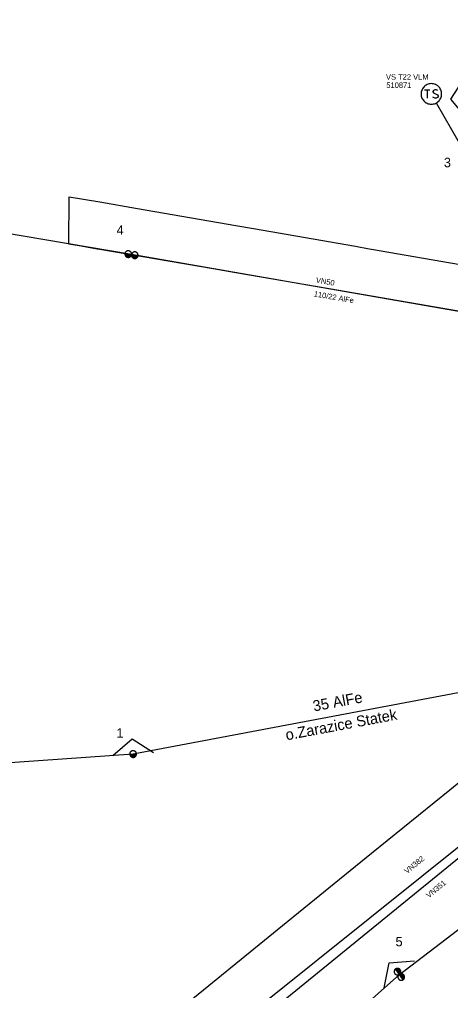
# Model space of a CAD drawing. Extents: x -545588 to -543214, y -1196037 to -1194452.
# Drawn here: x -545402.3 to -545323, y -1195024.5 to -1194845.7 of the extents above; entities that cross this region are included whole.
import ezdxf

# ---------------------------------------------------------------- set-up
doc = ezdxf.new("R2010")
doc.units = 0
for name, color, linetype in [('DOPLŇ_POPISY', 7, 'Continuous'), ('ELE_EON', 7, 'Continuous'), ('ELE_EON_POPIS', 7, 'Continuous'), ('POL_ZNAČKA_PRACOVNÍ', 7, 'Continuous'), ('SDEL_EON', 7, 'Continuous'), ('Vrstva 18', 7, 'Continuous'), ('Vrstva 25', 7, 'Continuous'), ('Vrstva 26', 7, 'Continuous'), ('Vrstva 27', 7, 'Continuous'), ('Vrstva 35', 7, 'Continuous'), ('Vrstva 52', 7, 'Continuous'), ('Vrstva 53', 7, 'Continuous'), ('Vrstva 54', 7, 'Continuous'), ('ZP_EON', 7, 'Continuous'), ('ZP_EON_POPIS', 7, 'Continuous')]:
    doc.layers.add(name, color=color, linetype=linetype)

# ---------------------------------------------------------------- blocks, each defined once
blk = doc.blocks.new('VN860')
at = {"layer": 'POL_ZNAČKA_PRACOVNÍ'}
for points in [[(-3.74, 0), (0.01, 2.82)], [(0.01, 2.82), (3.76, 0)]]:
    blk.add_lwpolyline(points, dxfattribs=at)
blk = doc.blocks.new('VN440')
at = {"layer": 'ELE_EON_POPIS'}
for points in [[(1.22, 0), (1.21, 0.13), (1.19, 0.25), (1.16, 0.38), (1.11, 0.5), (1.05, 0.61), (0.98, 0.72), (0.9, 0.82), (0.81, 0.91), (0.71, 0.99), (0.6, 1.06), (0.49, 1.12), (0.37, 1.16), (0.25, 1.2), (0.12, 1.22), (-0.01, 1.22), (-0.14, 1.22), (-0.26, 1.2), (-0.39, 1.16), (-0.51, 1.12), (-0.62, 1.06), (-0.73, 0.99), (-0.83, 0.91), (-0.92, 0.82), (-1, 0.72), (-1.07, 0.61), (-1.13, 0.5), (-1.18, 0.38), (-1.21, 0.25), (-1.23, 0.13), (-1.24, 0), (-1.23, -0.13), (-1.21, -0.26), (-1.18, -0.38), (-1.13, -0.5), (-1.07, -0.62), (-1, -0.73), (-0.92, -0.83), (-0.83, -0.92), (-0.73, -1), (-0.62, -1.07), (-0.51, -1.13), (-0.39, -1.17), (-0.26, -1.2), (-0.14, -1.23), (-0.01, -1.23), (0.12, -1.23), (0.25, -1.2), (0.37, -1.17), (0.49, -1.13), (0.6, -1.07), (0.71, -1), (0.81, -0.92), (0.9, -0.83), (0.98, -0.73), (1.05, -0.62), (1.11, -0.5), (1.16, -0.38), (1.19, -0.26), (1.21, -0.13), (1.22, 0)], [(-1.24, 0), (1.22, 0)], [(-1.18, -0.34), (1.1, -0.34)], [(-1.01, -0.63), (0.97, -0.63)], [(-0.74, -0.92), (0.68, -0.92)]]:
    blk.add_lwpolyline(points, dxfattribs=at)
blk = doc.blocks.new('VN450')
at = {"layer": 'ELE_EON_POPIS'}
for points in [[(0, 0), (-0.01, 0.13), (-0.03, 0.25), (-0.06, 0.38), (-0.11, 0.5), (-0.16, 0.61), (-0.23, 0.72), (-0.31, 0.82), (-0.4, 0.91), (-0.5, 0.99), (-0.61, 1.06), (-0.72, 1.11), (-0.84, 1.16), (-0.97, 1.19), (-1.09, 1.21), (-1.22, 1.22), (-1.35, 1.21), (-1.47, 1.19), (-1.59, 1.16), (-1.71, 1.11), (-1.83, 1.06), (-1.93, 0.99), (-2.03, 0.91), (-2.12, 0.82), (-2.2, 0.72), (-2.27, 0.61), (-2.33, 0.5), (-2.38, 0.38), (-2.41, 0.25), (-2.43, 0.13), (-2.44, 0), (-2.43, -0.13), (-2.41, -0.25), (-2.38, -0.38), (-2.33, -0.5), (-2.27, -0.61), (-2.2, -0.72), (-2.12, -0.82), (-2.03, -0.91), (-1.93, -0.99), (-1.83, -1.06), (-1.71, -1.11), (-1.59, -1.16), (-1.47, -1.19), (-1.35, -1.21), (-1.22, -1.22), (-1.09, -1.21), (-0.97, -1.19), (-0.84, -1.16), (-0.72, -1.11), (-0.61, -1.06), (-0.5, -0.99), (-0.4, -0.91), (-0.31, -0.82), (-0.23, -0.72), (-0.16, -0.61), (-0.11, -0.5), (-0.06, -0.38), (-0.03, -0.25), (-0.01, -0.13), (0, 0)], [(-2.44, 0), (2.44, 0)], [(2.44, 0), (2.43, 0.13), (2.41, 0.25), (2.38, 0.38), (2.33, 0.5), (2.27, 0.61), (2.2, 0.72), (2.12, 0.82), (2.03, 0.91), (1.94, 0.99), (1.83, 1.06), (1.71, 1.11), (1.6, 1.16), (1.47, 1.19), (1.35, 1.21), (1.22, 1.22), (1.09, 1.21), (0.97, 1.19), (0.84, 1.16), (0.72, 1.11), (0.61, 1.06), (0.5, 0.99), (0.4, 0.91), (0.31, 0.82), (0.23, 0.72), (0.16, 0.61), (0.11, 0.5), (0.06, 0.38), (0.03, 0.25), (0.01, 0.13), (0, 0), (0.01, -0.13), (0.03, -0.25), (0.06, -0.38), (0.11, -0.5), (0.16, -0.61), (0.23, -0.72), (0.31, -0.82), (0.4, -0.91), (0.5, -0.99), (0.61, -1.06), (0.72, -1.11), (0.84, -1.16), (0.97, -1.19), (1.09, -1.21), (1.22, -1.22), (1.35, -1.21), (1.47, -1.19), (1.6, -1.16), (1.71, -1.11), (1.83, -1.06), (1.94, -0.99), (2.03, -0.91), (2.12, -0.82), (2.2, -0.72), (2.27, -0.61), (2.33, -0.5), (2.38, -0.38), (2.41, -0.25), (2.43, -0.13), (2.44, 0)], [(-2.4, -0.31), (-0.04, -0.31)], [(-2.26, -0.61), (-0.17, -0.61)], [(-2.01, -0.92), (-0.42, -0.92)], [(0.04, -0.31), (2.4, -0.31)], [(0.17, -0.61), (2.27, -0.61)], [(0.42, -0.92), (2.02, -0.92)]]:
    blk.add_lwpolyline(points, dxfattribs=at)
blk = doc.blocks.new('VN610')
at = {"layer": 'ZP_EON_POPIS'}
for points in [[(1.88, 0), (1.87, 0.2), (1.84, 0.39), (1.79, 0.58), (1.72, 0.77), (1.63, 0.94), (1.52, 1.11), (1.4, 1.26), (1.26, 1.4), (1.1, 1.53), (0.94, 1.63), (0.76, 1.72), (0.58, 1.8), (0.39, 1.85), (0.19, 1.88), (-0.01, 1.89), (-0.21, 1.88), (-0.4, 1.85), (-0.59, 1.8), (-0.78, 1.72), (-0.95, 1.63), (-1.12, 1.53), (-1.27, 1.4), (-1.41, 1.26), (-1.54, 1.11), (-1.64, 0.94), (-1.73, 0.77), (-1.8, 0.58), (-1.86, 0.39), (-1.89, 0.2), (-1.9, 0), (-1.89, -0.2), (-1.86, -0.39), (-1.8, -0.58), (-1.73, -0.77), (-1.64, -0.95), (-1.54, -1.11), (-1.41, -1.27), (-1.27, -1.41), (-1.12, -1.53), (-0.95, -1.64), (-0.78, -1.73), (-0.59, -1.8), (-0.4, -1.85), (-0.21, -1.88), (-0.01, -1.89), (0.19, -1.88), (0.39, -1.85), (0.58, -1.8), (0.76, -1.73), (0.94, -1.64), (1.1, -1.53), (1.26, -1.41), (1.4, -1.27), (1.52, -1.11), (1.63, -0.95), (1.72, -0.77), (1.79, -0.58), (1.84, -0.39), (1.87, -0.2), (1.88, 0)], [(-1.27, 0.78), (-0.26, 0.78)], [(-0.76, 0.78), (-0.76, -0.79)], [(1.19, 0.66), (0.94, 0.78), (0.62, 0.78), (0.37, 0.66), (0.24, 0.47), (0.24, 0.4), (0.37, 0.22), (1.12, -0.16), (1.25, -0.32), (1.25, -0.48), (1.12, -0.67), (0.87, -0.79), (0.62, -0.79), (0.49, -0.73), (0.24, -0.6)]]:
    blk.add_lwpolyline(points, dxfattribs=at)

msp = doc.modelspace()

# ---------------------------------------------------------------- linework, layer by layer
at = {"layer": 'ELE_EON'}
for points in [[(-545292.28, -1194904.3), (-545301.79, -1194902.92), (-545381.67, -1194889.04), (-545464.66, -1194874.97), (-545546.4, -1194860.3), (-545587.31, -1194845.75)], [(-545395.75, -1195077.92), (-545332.4, -1195021.48), (-545278.54, -1194980.38), (-545246.49, -1194956.34)], [(-545290.02, -1194972.8), (-545405.11, -1195065.07), (-545495.54, -1195139.14), (-545571.44, -1195160.65)], [(-545289.27, -1194973.82), (-545403.67, -1195067.08), (-545494.32, -1195141.28), (-545571.32, -1195163.18)]]:
    msp.add_lwpolyline(points, dxfattribs=at)
at = {"layer": 'Vrstva 35'}
for points in [[(-545312.5, -1194900.99), (-545324.01, -1194899.01), (-545337.5, -1194896.69), (-545345.34, -1194895.34), (-545362.5, -1194892.39), (-545366.67, -1194891.67), (-545387.5, -1194888.09), (-545388.01, -1194888.01), (-545390.95, -1194887.5), (-545393.22, -1194887.11), (-545393.11, -1194878.37), (-545387.5, -1194879.34), (-545380.55, -1194880.55), (-545362.5, -1194883.68), (-545359.24, -1194884.24), (-545340.46, -1194887.5), (-545337.94, -1194887.94), (-545337.5, -1194888.01), (-545316.63, -1194891.63)], [(-545384.64, -1195037.5), (-545362.5, -1195019.51), (-545353.87, -1195012.5), (-545337.5, -1194999.2), (-545323.09, -1194987.5), (-545312.5, -1194978.9)]]:
    msp.add_lwpolyline(points, dxfattribs=at)
at = {"layer": 'Vrstva 52'}
for points in [[(-545318.54, -1194873.42), (-545325.57, -1194861.13)], [(-545295.62, -1194964.78), (-545381.37, -1194980.94), (-545453.74, -1194986.07), (-545493.42, -1194989.16)]]:
    msp.add_lwpolyline(points, dxfattribs=at)
at = {"layer": 'ZP_EON'}
msp.add_lwpolyline([(-545319.76, -1194855.37), (-545323.02, -1194860.43), (-545310.99, -1194874.79)], dxfattribs=at)

# ---------------------------------------------------------------- block references
at = {"layer": 'DOPLŇ_POPISY'}
for name, p, xscale, yscale, rotation in [('VN450', (-545381.67, -1194889.04), 0.5, 0.5, -9.622102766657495), ('VN440', (-545381.37, -1194980.94), 0.5, 0.5000000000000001, 4.054341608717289), ('VN450', (-545332.4, -1195021.48), 0.49999999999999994, 0.5000000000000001, 125.22301664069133)]:
    msp.add_blockref(name, p, dxfattribs=dict(at, xscale=xscale, yscale=yscale, rotation=rotation))
at = {"layer": 'Vrstva 18'}
for p, rotation in [((-545381.37, -1194980.94), 4.054836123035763), ((-545332.4, -1195021.48), 41.696461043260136)]:
    msp.add_blockref('VN860', p, dxfattribs=dict(at, rotation=rotation))
at = {"layer": 'Vrstva 25', "rotation": -0.058288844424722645}
msp.add_blockref('VN610', (-545326.51, -1194859.46), dxfattribs=at)

# ---------------------------------------------------------------- texts
at = {"layer": 'ELE_EON_POPIS'}
msp.add_text('110/22 AlFe', height=1, rotation=350.143, dxfattribs=at).set_placement((-545348.2, -1194896.71))
at = {"layer": 'POL_ZNAČKA_PRACOVNÍ'}
for s, p in [('3', (-545324.22, -1194872.95)), ('4', (-545384.42, -1194885.38)), ('1', (-545384.44, -1194977.95)), ('5', (-545333.11, -1195016.33))]:
    msp.add_text(s, height=1.75, dxfattribs=at).set_placement(p)
at = {"layer": 'SDEL_EON'}
for s, rotation, p in [('VN50', 350.143, (-545347.81, -1194894.17)), ('VN382', 39.181, (-545330.99, -1195003.04)), ('VN351', 39.19, (-545326.98, -1195007.49))]:
    msp.add_text(s, height=1, rotation=rotation, dxfattribs=at).set_placement(p)
at = {"layer": 'Vrstva 26'}
msp.add_text('510871', height=1, dxfattribs=at).set_placement((-545334.8, -1194858.35))
at = {"layer": 'Vrstva 27'}
msp.add_text('VS T22 VLM', height=1, dxfattribs=at).set_placement((-545334.86, -1194856.84))
at = {"layer": 'Vrstva 53'}
msp.add_text('35 AlFe', height=2, rotation=10.647, dxfattribs=at).set_placement((-545348.12, -1194973.12))
at = {"layer": 'Vrstva 54'}
msp.add_text('o.Zarazice Statek', height=2, rotation=10.647, dxfattribs=at).set_placement((-545353.15, -1194978.43))

doc.saveas('drawing.dxf')
